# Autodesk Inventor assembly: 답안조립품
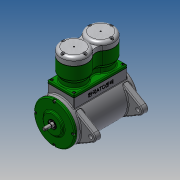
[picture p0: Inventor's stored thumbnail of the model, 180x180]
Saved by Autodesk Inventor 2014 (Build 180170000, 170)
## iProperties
Created: 2019-08
Part Number: 답안조립품
Document SubType Name: Assembly
Designer: kb542
Mass: 7629.46 g
Surface Area: 5241.59 cm^2
Volume: 2149.39 cm^3
Density: 3.5496 g/cm^3
Author: kb542
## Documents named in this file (18)
- C:\Users\kb542\Desktop\390804V1039\답안조립품.iam
- C:\Users\kb542\Desktop\390804V1039\본체.ipt
- C:\Users\kb542\Desktop\390804V1039\앞커버.ipt
- C:\Users\kb542\Desktop\390804V1039\크랭크축.ipt
- C:\Users\kb542\Desktop\390804V1039\베어링 12 x 28 x 8.ipt
- C:\Users\kb542\Desktop\390804V1039\오일 실 12 25 7.ipt
- C:\Users\kb542\Desktop\390804V1039\실린더 개스킷.ipt
- C:\Users\kb542\Desktop\390804V1039\실린더.ipt
- C:\Users\kb542\Desktop\390804V1039\피스톤.ipt
- C:\Users\kb542\Desktop\390804V1039\피스톤핀.ipt
- C:\Users\kb542\Desktop\390804V1039\커넥팅로드.ipt
- C:\Users\kb542\Desktop\390804V1039\커넥팅로드 엔드.ipt
- C:\Users\kb542\Desktop\390804V1039\육각 머리 볼트 M4 x 16.ipt
- C:\Users\kb542\Desktop\390804V1039\너트 M4.ipt
- C:\Users\kb542\Desktop\390804V1039\실린더헤드 개스킷.ipt
- C:\Users\kb542\Desktop\390804V1039\실린더헤드.ipt
- C:\Users\kb542\Desktop\390804V1039\볼트 M4 x 8.ipt
- C:\Users\kb542\Desktop\390804V1039\볼트 M5 x 20.ipt
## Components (4 placed, 2 different names)
1. 피스톤:1
2. 피스톤:2
3. 피스톤핀:1
4. 피스톤핀:2
